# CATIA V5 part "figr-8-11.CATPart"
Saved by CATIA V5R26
Part number: Part2
Bounding box of the stored display mesh (mm): x -37.886 to 37.886, y -61.415 to 61.415, z 29 to 58
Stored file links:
  D:\_Deepak\CATIA\CATIA V5-6R2016_Deepak\Resources\Part files\Partfiles\c08_catia_v5_6r2016_prt\figr-8-11.CATPart
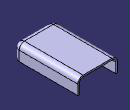
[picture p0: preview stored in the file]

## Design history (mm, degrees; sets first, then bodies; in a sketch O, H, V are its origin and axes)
Body1 (main body)
  Sketch1 on xy-plane, origin (0, 0, 0), H (1, 0, 0), V (0, 1, 0)
    line L1 (37.8862, 61.4155) -> (37.8862, -61.4155)
    line L2 (37.8862, -61.4155) -> (-37.8862, -61.4155)
    line L3 (-37.8862, -61.4155) -> (-37.8862, 61.4155)
    line L4 (-37.8862, 61.4155) -> (37.8862, 61.4155)
    vertical: L1 V, L3 V
    horizontal: L2 H, L4 H
    equidistance: L1 L3 O, L2 L4 O
  Pad1: profile Sketch1, direction (0, 0, 1), length 29
  Fillet1: radius 10, on edge [face of Pad1 | face of Pad1] (x5)
  Shell1: ExtOffset 0, Face (face of Pad1; face of Pad1), IntOffset 3
  Symmetry1: ToTransfor Shell1, Reference face of Pad1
